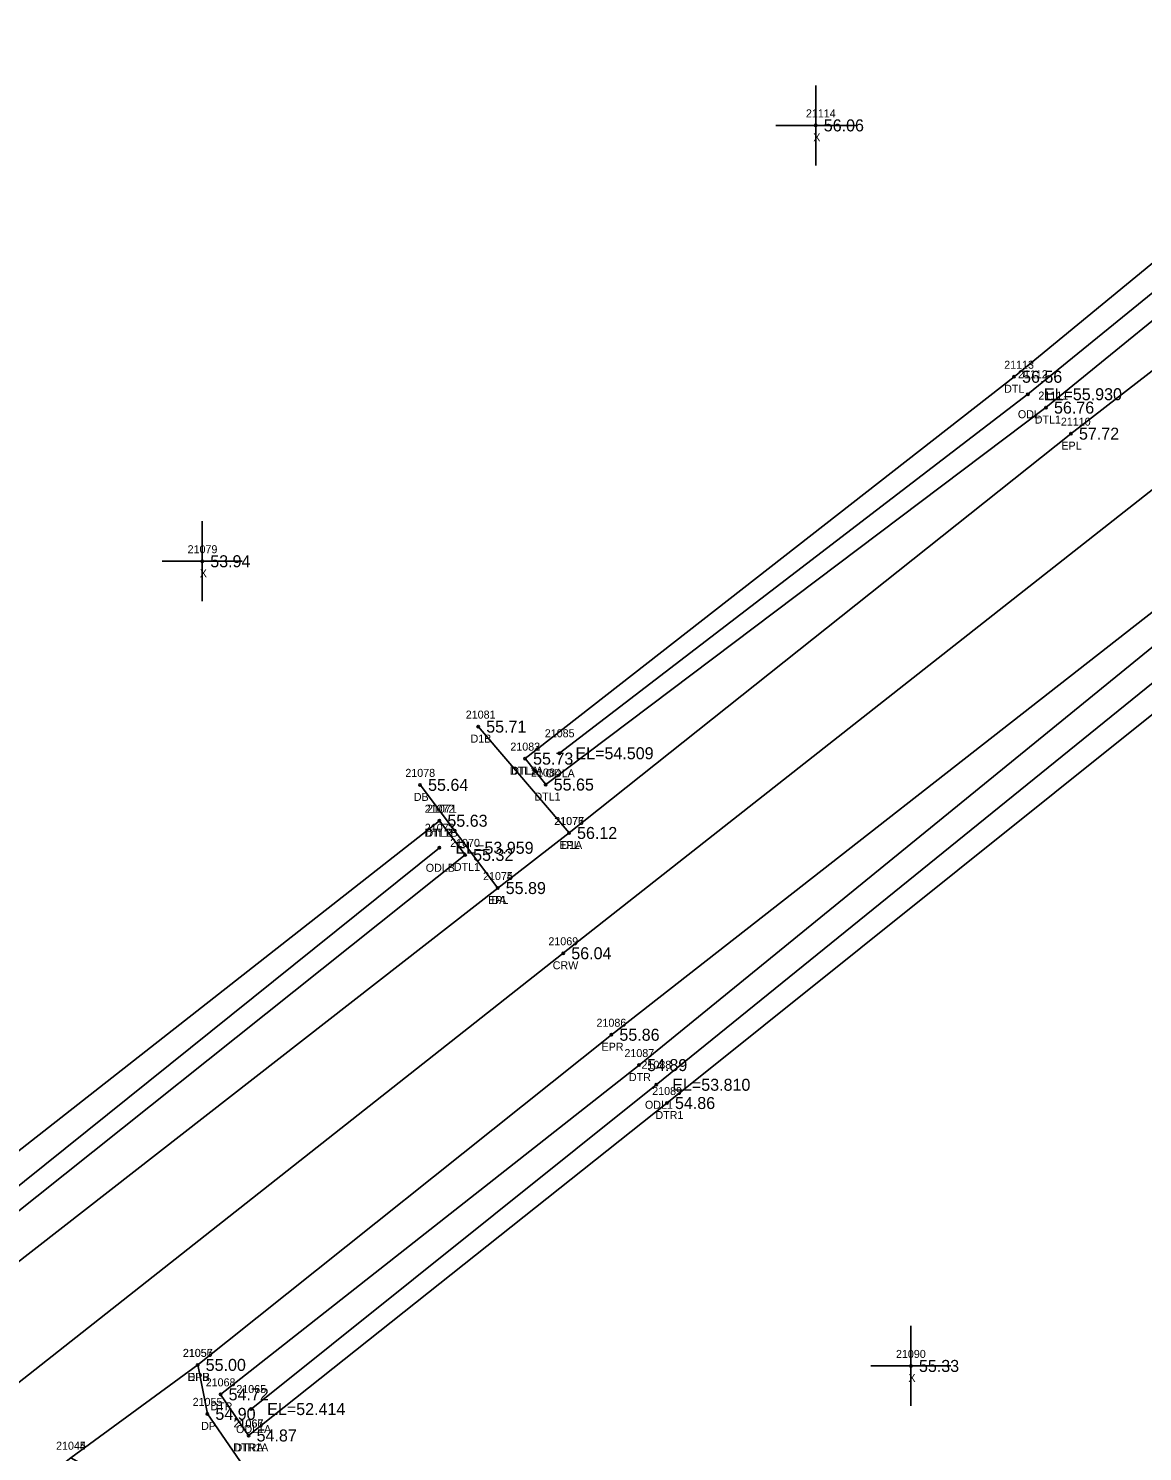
# Model space of a CAD drawing. Extents: x 2420351 to 2422725, y 845330 to 846558.
# Drawn here: x 2422224.3 to 2422363.4, y 846134.8 to 846312.6 of the extents above; entities that cross this region are included whole.
import ezdxf

# ---------------------------------------------------------------- set-up
doc = ezdxf.new("R2010")
doc.units = 0
for name, color, linetype in [('RD_DTM_BkLn1', 7, 'Continuous'), ('RD_EX_Driveway', 7, 'Continuous'), ('RD_EX_Driveway_txCode', 7, 'Continuous'), ('RD_EX_H2O', 7, 'Continuous'), ('RD_EX_H2O_txCode', 7, 'Continuous'), ('RD_EX_Misc', 7, 'Continuous'), ('RD_EX_Misc_txCode', 7, 'Continuous'), ('RD_EX_Road', 7, 'Continuous'), ('RD_EX_Road_txCode', 7, 'Continuous'), ('RD_EX_TX_Driveway_ELEV', 7, 'Continuous'), ('RD_EX_TX_H2O_ELEV', 7, 'Continuous'), ('RD_EX_TX_Misc_ELEV', 7, 'Continuous'), ('RD_EX_TX_Road_ELEV', 7, 'Continuous'), ('RD_HC_Survey_ELEV', 7, 'Continuous'), ('RD_HC_Survey_txCode', 7, 'Continuous'), ('RD_SMD_Locator', 7, 'Continuous')]:
    doc.layers.add(name, color=color, linetype=linetype)

msp = doc.modelspace()

# ---------------------------------------------------------------- linework, layer by layer
at = {"layer": 'RD_DTM_BkLn1'}
msp.add_lwpolyline([(2421809.69, 845832.82), (2421858.88, 845863.61), (2421946.63, 845925.83), (2421988.11, 845958.04), (2422060.85, 846015.47), (2422145.87, 846082.37), (2422217.73, 846139.26), (2422291.07, 846197.06), (2422441.76, 846315.63), (2422509.48, 846369.12), (2422585.38, 846428.46), (2422650.19, 846479.15)], dxfattribs=at)
at = {"layer": 'RD_EX_Driveway'}
for p, q in [((2422291.79, 846212.09), (2422280.44, 846225.38)), ((2422282.88, 846205.21), (2422273.18, 846218.1))]:
    msp.add_line(p, q, dxfattribs=at)
msp.add_lwpolyline([(2422229.55, 846134.03), (2422238.02, 846129.35), (2422244.49, 846122.41), (2422252.96, 846130.33), (2422246.61, 846139.51), (2422245.4, 846145.63)], dxfattribs=at)
at = {"layer": 'RD_EX_H2O'}
for points in [[(2422286.3, 846221.38), (2422347.38, 846269.09), (2422394.86, 846308.12)], [(2422286.3, 846221.38), (2422288.87, 846218.14), (2422351.37, 846265.24), (2422397.58, 846302.88), (2422398.48, 846307.09), (2422394.86, 846308.12)], [(2422290.59, 846222.05), (2422349.1, 846266.91), (2422395.94, 846305.01)], [(2422251.76, 846136.81), (2422248.26, 846141.95), (2422300.54, 846183.09), (2422372, 846241.31)], [(2422251.76, 846136.81), (2422304.02, 846178.35), (2422376.7, 846236.57), (2422372, 846241.31)], [(2422252.08, 846140.11), (2422302.68, 846180.63), (2422372.63, 846237.25)], [(2422081.44, 846056.32), (2422081.97, 846059.2), (2422133.38, 846102.53), (2422202.76, 846156.5), (2422275.59, 846213.62)], [(2422084.34, 846055.89), (2422136.63, 846097.46), (2422207.35, 846152.39), (2422278.81, 846209.35), (2422275.59, 846213.62)], [(2422081.44, 846056.32), (2422134.7, 846099.84), (2422205.52, 846153.98), (2422275.6, 846210.24)]]:
    msp.add_lwpolyline(points, dxfattribs=at)
at = {"layer": 'RD_EX_Misc'}
for p, q in [((2422322.61, 846295.5), (2422322.61, 846305.5)), ((2422317.61, 846300.5), (2422327.61, 846300.5)), ((2422245.97, 846241.04), (2422245.97, 846251.04)), ((2422240.97, 846246.04), (2422250.97, 846246.04)), ((2422334.5, 846140.5), (2422334.5, 846150.5)), ((2422329.5, 846145.5), (2422339.5, 846145.5))]:
    msp.add_line(p, q, dxfattribs=at)
at = {"layer": 'RD_EX_Road'}
for points in [[(2421810.77, 845819.82), (2421809.69, 845832.82), (2421803.88, 845842.86), (2421852.96, 845873.69), (2421939.48, 845935.12), (2421980.78, 845967.01), (2422140.12, 846092.81), (2422210.03, 846148.43), (2422282.88, 846205.21), (2422291.79, 846212.09), (2422354.49, 846261.98), (2422400.82, 846297.88), (2422417.34, 846311.65), (2422435.4, 846324.77), (2422462.49, 846346.77), (2422472.85, 846354.85), (2422502.3, 846378.16), (2422578.05, 846437.54), (2422605.64, 846459.09), (2422626.64, 846476.17), (2422642.61, 846488.86)], [(2421810.77, 845819.82), (2421865.31, 845853.52), (2421953.26, 845916.07), (2421995.06, 845948.03), (2422068.36, 846005.98), (2422153.46, 846073.36), (2422229.55, 846134.03), (2422245.4, 846145.63), (2422297.08, 846186.88), (2422369.77, 846243.69), (2422382.04, 846253.08), (2422449.02, 846305.97), (2422517.14, 846360.1), (2422592.58, 846419.1), (2422657.51, 846470.1)]]:
    msp.add_lwpolyline(points, dxfattribs=at)
at = {"layer": 'RD_SMD_Locator'}
for centre in [(2422322.61, 846300.5), (2422347.38, 846269.09), (2422349.1, 846266.91), (2422351.37, 846265.24), (2422354.49, 846261.98), (2422245.97, 846246.04), (2422280.44, 846225.38), (2422286.3, 846221.38), (2422286.3, 846221.38), (2422290.59, 846222.05), (2422273.18, 846218.1), (2422288.87, 846218.14), (2422275.59, 846213.62), (2422275.59, 846213.62), (2422291.79, 846212.09), (2422291.79, 846212.09), (2422275.6, 846210.24), (2422278.81, 846209.35), (2422282.88, 846205.21), (2422282.88, 846205.21), (2422291.07, 846197.06), (2422297.08, 846186.88), (2422300.54, 846183.09), (2422302.68, 846180.63), (2422304.02, 846178.35), (2422245.4, 846145.63), (2422245.4, 846145.63), (2422334.5, 846145.5), (2422248.26, 846141.95), (2422246.61, 846139.51), (2422252.08, 846140.11), (2422251.76, 846136.81), (2422251.76, 846136.81)]:
    msp.add_circle(centre, 0.15, dxfattribs=at)

# ---------------------------------------------------------------- texts
at = {"layer": 'RD_EX_Driveway_txCode'}
for s, p in [('21081', (2422278.89, 846226.38)), ('D1B', (2422279.49, 846223.38)), ('21078', (2422271.34, 846219.1)), ('DB', (2422272.4, 846216.1)), ('21077', (2422289.95, 846213.09)), ('D1A', (2422290.83, 846210.09)), ('21075', (2422281.05, 846206.21)), ('DA', (2422282.09, 846203.21)), ('21057', (2422243.56, 846146.63)), ('DPB', (2422244.14, 846143.63)), ('21055', (2422244.77, 846140.51)), ('DP', (2422245.83, 846137.51)), ('21045', (2422227.71, 846135.03))]:
    msp.add_text(s, height=1, dxfattribs=at).set_placement(p)
at = {"layer": 'RD_EX_H2O_txCode'}
for s, p in [('21113', (2422346.15, 846270.09)), ('21112', (2422347.87, 846268.91)), ('DTL', (2422346.14, 846267.09)), ('21111', (2422350.42, 846266.24)), ('ODL', (2422347.86, 846263.91)), ('DTL1', (2422349.96, 846263.24)), ('21085', (2422288.76, 846224.05)), ('21082', (2422284.46, 846222.38)), ('21083', (2422284.46, 846222.38)), ('DTL1A', (2422284.4, 846219.38)), ('DTLA', (2422284.57, 846219.38)), ('21084', (2422287.04, 846219.14)), ('ODLA', (2422288.86, 846219.05)), ('DTL1', (2422287.46, 846216.14)), ('21072', (2422273.76, 846214.62)), ('21071', (2422274.04, 846214.62)), ('DTL1B', (2422273.71, 846211.62)), ('21073', (2422273.77, 846212.24)), ('DTLB', (2422273.87, 846211.62)), ('21070', (2422276.94, 846210.35)), ('ODLB', (2422273.89, 846207.24)), ('DTL1', (2422277.4, 846207.35)), ('21087', (2422298.71, 846184.09)), ('21088', (2422300.84, 846182.63)), ('DTR', (2422299.27, 846181.09)), ('21089', (2422302.18, 846179.35)), ('ODL1', (2422301.27, 846177.63)), ('DTR1', (2422302.58, 846176.35)), ('21068', (2422246.4, 846142.95)), ('21065', (2422250.23, 846142.11)), ('DTR', (2422246.99, 846139.95)), ('21066', (2422249.87, 846137.81)), ('21067', (2422249.9, 846137.81)), ('ODL1A', (2422250.19, 846137.11)), ('DTR1A', (2422249.84, 846134.81)), ('DTRA', (2422250, 846134.81))]:
    msp.add_text(s, height=1, dxfattribs=at).set_placement(p)
at = {"layer": 'RD_EX_Misc_txCode'}
for s, p in [('21114', (2422321.38, 846301.5)), ('X', (2422322.3, 846298.5)), ('21079', (2422244.14, 846247.04)), ('X', (2422245.66, 846244.04)), ('21090', (2422332.63, 846146.5)), ('X', (2422334.19, 846143.5))]:
    msp.add_text(s, height=1, dxfattribs=at).set_placement(p)
at = {"layer": 'RD_EX_Road_txCode'}
for s, p in [('21110', (2422353.23, 846262.98)), ('EPL', (2422353.29, 846259.98)), ('21076', (2422289.93, 846213.09)), ('EPL', (2422290.58, 846210.09)), ('21074', (2422281.05, 846206.21)), ('EPL', (2422281.68, 846203.21)), ('21086', (2422295.22, 846187.88)), ('EPR', (2422295.85, 846184.88)), ('21056', (2422243.54, 846146.63)), ('EPR', (2422244.17, 846143.63)), ('21044', (2422227.71, 846135.03))]:
    msp.add_text(s, height=1, dxfattribs=at).set_placement(p)
at = {"layer": 'RD_EX_TX_Driveway_ELEV'}
for s, p in [('55.71', (2422281.44, 846224.63)), ('55.64', (2422274.18, 846217.35)), ('56.12', (2422292.79, 846211.34)), ('55.89', (2422283.88, 846204.46)), ('55.00', (2422246.4, 846144.88)), ('54.90', (2422247.61, 846138.76))]:
    msp.add_text(s, height=1.5, dxfattribs=at).set_placement(p)
at = {"layer": 'RD_EX_TX_H2O_ELEV'}
for s, p in [('56.56', (2422348.38, 846268.34)), ('EL=55.930', (2422351.1, 846266.16)), ('56.76', (2422352.37, 846264.49)), ('EL=54.509', (2422292.59, 846221.3)), ('55.73', (2422287.3, 846220.63)), ('55.73', (2422287.3, 846220.63)), ('55.65', (2422289.87, 846217.39)), ('55.63', (2422276.59, 846212.87)), ('55.63', (2422276.59, 846212.87)), ('EL=53.959', (2422277.6, 846209.49)), ('55.32', (2422279.81, 846208.6)), ('54.89', (2422301.54, 846182.34)), ('EL=53.810', (2422304.68, 846179.88)), ('54.86', (2422305.02, 846177.6)), ('54.72', (2422249.26, 846141.2)), ('EL=52.414', (2422254.08, 846139.36)), ('54.87', (2422252.76, 846136.06)), ('54.87', (2422252.76, 846136.06))]:
    msp.add_text(s, height=1.5, dxfattribs=at).set_placement(p)
at = {"layer": 'RD_EX_TX_Misc_ELEV'}
for s, p in [('56.06', (2422323.61, 846299.75)), ('53.94', (2422246.97, 846245.29)), ('55.33', (2422335.5, 846144.75))]:
    msp.add_text(s, height=1.5, dxfattribs=at).set_placement(p)
at = {"layer": 'RD_EX_TX_Road_ELEV'}
for s, p in [('57.72', (2422355.49, 846261.23)), ('56.12', (2422292.79, 846211.34)), ('55.89', (2422283.88, 846204.46)), ('55.86', (2422298.08, 846186.13)), ('55.00', (2422246.4, 846144.88))]:
    msp.add_text(s, height=1.5, dxfattribs=at).set_placement(p)
at = {"layer": 'RD_HC_Survey_ELEV'}
msp.add_text('56.04', height=1.5, dxfattribs=at).set_placement((2422292.07, 846196.31))
at = {"layer": 'RD_HC_Survey_txCode'}
for s, p in [('21069', (2422289.21, 846198.06)), ('CRW', (2422289.75, 846195.06))]:
    msp.add_text(s, height=1, dxfattribs=at).set_placement(p)

doc.saveas('drawing.dxf')
